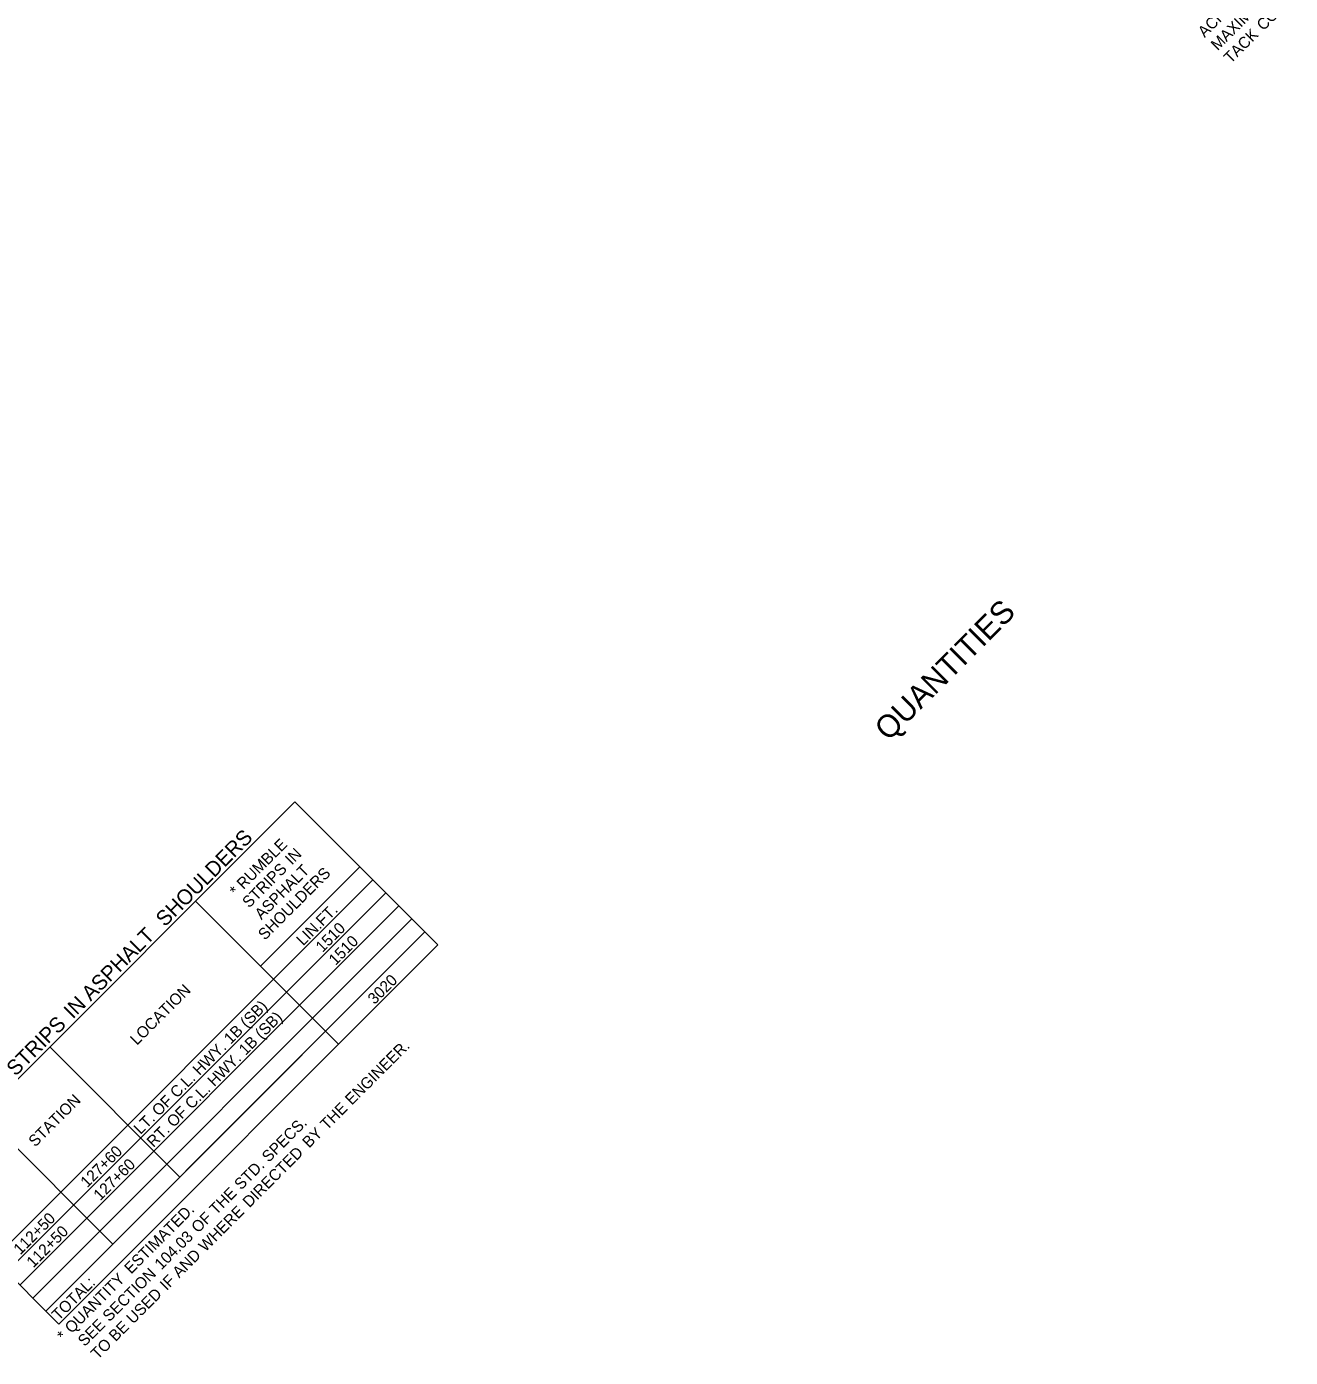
# Model space of a CAD drawing. Extents: x 1675667 to 1681231, y 227227 to 232694.
# Drawn here: x 1678183 to 1678853, y 229074 to 229780 of the extents above; entities that cross this region are included whole.
import ezdxf

# ---------------------------------------------------------------- set-up
doc = ezdxf.new("R2010")
doc.units = 0
doc.layers.add('Default', color=7, linetype='Continuous')
doc.layers.add('R_Annotation', color=7, linetype='Continuous')

msp = doc.modelspace()

# ---------------------------------------------------------------- linework, layer by layer
at = {"layer": 'Default'}
for p, q in [((1678124.36, 229167.83), (1678325.31, 229368.82)), ((1678401.15, 229292.99), (1678325.31, 229368.82)), ((1678401.15, 229292.99), (1678325.31, 229368.82)), ((1678307.05, 229281.61), (1678359.78, 229334.36)), ((1678165.73, 229126.47), (1678366.68, 229327.46)), ((1678172.63, 229119.58), (1678373.57, 229320.57)), ((1678179.52, 229112.68), (1678380.47, 229313.68)), ((1678348.42, 229240.25), (1678272.57, 229316.07)), ((1678186.42, 229105.79), (1678387.36, 229306.78)), ((1678264.32, 229169.91), (1678394.26, 229299.89)), ((1678200.21, 229092), (1678401.15, 229292.99)), ((1678193.32, 229098.89), (1678341.52, 229247.14)), ((1678264.32, 229169.91), (1678195.37, 229238.85)), ((1678264.32, 229169.91), (1678195.37, 229238.85)), ((1678228.82, 229134.4), (1678159.87, 229203.34)), ((1678228.82, 229134.4), (1678159.87, 229203.34)), ((1678193.32, 229098.89), (1678264.32, 229169.91)), ((1678200.21, 229092), (1678124.36, 229167.83)), ((1678200.21, 229092), (1678124.36, 229167.83))]:
    msp.add_line(p, q, dxfattribs=at)

# ---------------------------------------------------------------- texts
for s, height, p in [('MAXIMUM', 6, (1678814.45, 229766.57)), (' COAT', 6, (1678837.14, 229775.48)), ('ACHM', 6, (1678807.55, 229773.47)), ('TACK', 6, (1678821.34, 229759.68)), (' SHOULDERS', 8, (1678254.28, 229300.04)), (' RUMBLE', 6, (1678296.49, 229320.37)), (' IN', 6, (1678322.13, 229333.29)), ('STRIPS', 6, (1678301.01, 229312.16)), ('ASPHALT', 6, (1678307.55, 229305.97)), ('SHOULDERS', 6, (1678309.38, 229295.08)), ('*', 6, (1678294.31, 229318.19)), ('LIN.FT.', 6, (1678329.63, 229292.1)), (' ASPHALT', 8, (1678214.93, 229260.68)), ('1510', 6, (1678339.91, 229288.59)), ('1510', 6, (1678346.81, 229281.7)), ('3020', 6, (1678367.49, 229261.02)), ('LOCATION', 6, (1678241.54, 229239.42)), (' IN', 8, (1678205.46, 229251.21)), (' (SB)', 6, (1678298.3, 229246.97)), (' STRIPS', 8, (1678175.11, 229220.85)), (' (SB)', 6, (1678306.18, 229241.07)), (' 1B', 6, (1678289.72, 229238.39)), (' HWY.', 6, (1678273.12, 229221.79)), (' 1B', 6, (1678297.6, 229232.49)), (' ENGINEER.', 6, (1678353.94, 229206.1)), (' HWY.', 6, (1678281, 229215.88)), (' C.L.', 6, (1678261.12, 229209.79)), ('STATION', 6, (1678187.65, 229185.52)), (' OF', 6, (1678251.52, 229200.18)), (' C.L.', 6, (1678269.01, 229203.88)), (' OF', 6, (1678259.4, 229194.27)), (' THE', 6, (1678340.76, 229192.91)), ('LT.', 6, (1678243.47, 229192.13)), ('RT.', 6, (1678250.37, 229185.24)), (' SPECS.', 6, (1678309.82, 229175.75)), (' BY', 6, (1678331.25, 229183.4)), ('127+60', 6, (1678215.21, 229163.86)), (' DIRECTED', 6, (1678299.62, 229151.76)), ('127+60', 6, (1678222.1, 229156.97)), (' STD.', 6, (1678295.19, 229161.12)), (' THE', 6, (1678282, 229147.93)), (' WHERE', 6, (1678276.23, 229128.36)), ('112+50', 6, (1678179.71, 229128.35)), (' ESTIMATED.', 6, (1678236.87, 229116.58)), (' OF', 6, (1678272.39, 229138.32)), ('112+50', 6, (1678186.6, 229121.46)), (' 104.03', 6, (1678252.9, 229118.82)), (' AND', 6, (1678262.38, 229114.51)), ('QUANTITY', 6, (1678206.95, 229086.65)), (' SECTION', 6, (1678225.39, 229091.3)), ('TOTAL:', 6, (1678200.05, 229093.54)), (' IF', 6, (1678255.74, 229107.87)), (' USED', 6, (1678237.94, 229090.07)), ('SEE', 6, (1678213.84, 229079.75)), (' BE', 6, (1678228.7, 229080.83)), ('*', 6, (1678202.81, 229082.51)), ('TO', 6, (1678220.74, 229072.86))]:
    msp.add_text(s, height=height, rotation=45.00703, dxfattribs=at).set_placement(p)
at = {"layer": 'R_Annotation'}
msp.add_text('QUANTITIES', height=12, rotation=45.00704, dxfattribs=at).set_placement((1678639.93, 229400.47))

doc.saveas('drawing.dxf')
